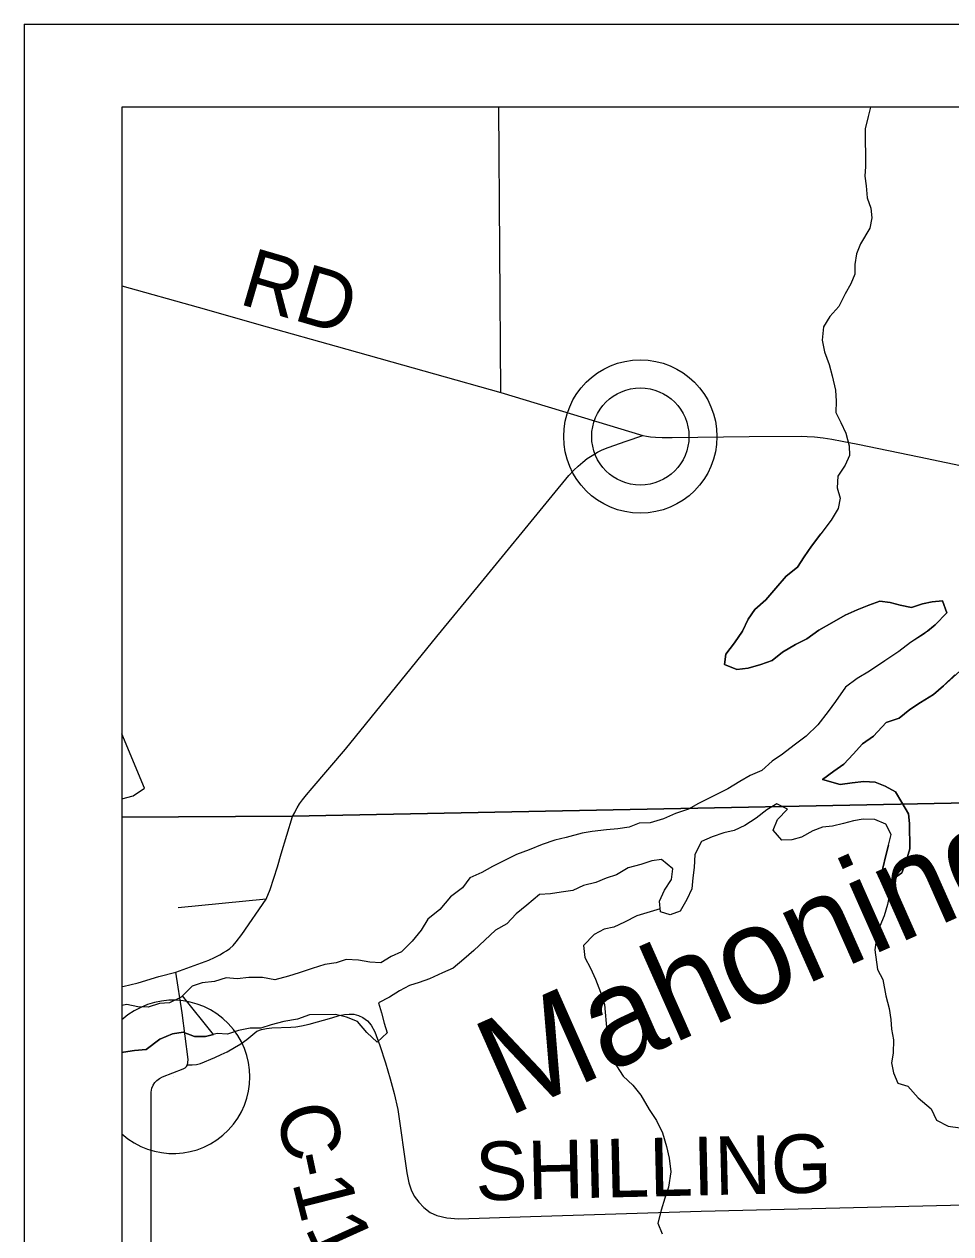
# Model space of a CAD drawing. Extents: x 0 to 34, y 0 to 22.
# Drawn here: x 2.895 to 3.794, y 19.713 to 20.887 of the extents above; entities that cross this region are included whole.
import ezdxf

# ---------------------------------------------------------------- set-up
doc = ezdxf.new("R2010")
doc.units = 0
for name, color, linetype in [('GM_X_Corporation', 7, 'Continuous'), ('GM_X_County_Road', 7, 'Continuous'), ('GM_X_County_Road_Text', 7, 'Continuous'), ('GM_X_Major_Lake', 7, 'Continuous'), ('GM_X_Major_River_Text', 7, 'Continuous'), ('GM_X_Minor_Lake', 7, 'Continuous'), ('GM_X_Minor_River', 7, 'Continuous'), ('GM_X_Township_Road', 7, 'Continuous'), ('GM_X_Unincorporated', 7, 'Continuous'), ('GM_X_Unincorporated_Location', 7, 'Continuous'), ('SH_Data', 7, 'Continuous')]:
    doc.layers.add(name, color=color, linetype=linetype)

msp = doc.modelspace()

# ---------------------------------------------------------------- linework, layer by layer
at = {"layer": 'GM_X_Corporation'}
msp.add_lwpolyline([(7.2136, 20.8069), (2.9895, 20.8069), (2.9895, 20.1176), (3.1549, 20.1187), (4.9925, 20.1548), (5.7004, 20.168), (6.0786, 20.1754), (7.2254, 20.198), (7.2157, 20.6753), (7.2146, 20.7526)], close=True, dxfattribs=at)
msp.add_lwpolyline([(7.2872, 17.1772), (7.283, 17.3071), (7.2799, 17.4174), (7.2764, 17.5202), (7.2751, 17.5764), (7.2467, 19.0557), (7.2468, 19.0896), (7.2426, 19.2998), (7.2392, 19.4543), (7.237, 19.6097), (7.2344, 19.7492), (7.2317, 19.8848), (7.2291, 20.0061), (7.2266, 20.122), (7.2254, 20.198), (6.0786, 20.1754), (5.7004, 20.168), (4.9925, 20.1548), (3.1549, 20.1187), (2.9895, 20.1176), (2.9895, 14.989)], dxfattribs=at)
at = {"layer": 'GM_X_County_Road'}
for points in [[(2.9895, 20.6334), (3.0636, 20.6128), (3.1305, 20.5937), (3.1975, 20.5748), (3.293, 20.5479), (3.3574, 20.5298), (3.4952, 20.4881)], [(3.4952, 20.4881), (3.4988, 20.4874), (3.5026, 20.4869), (3.5076, 20.4866), (3.514, 20.4862), (3.5236, 20.4863), (3.5983, 20.487), (3.6493, 20.4874), (3.6549, 20.4872), (3.662, 20.4867), (3.6704, 20.4858), (3.6788, 20.4846), (3.6888, 20.4827), (3.7038, 20.4797), (3.7635, 20.4674), (3.8622, 20.4468)], [(3.053, 19.8774), (3.0535, 19.8797), (3.0537, 19.8826), (3.0479, 19.9276), (3.0419, 19.9673)], [(3.053, 19.8774), (3.0575, 19.8772), (3.0617, 19.8776), (3.0656, 19.8785), (3.0796, 19.8845), (3.0857, 19.8872), (3.0917, 19.89), (3.0989, 19.894), (3.1048, 19.8978), (3.1108, 19.9018), (3.1205, 19.9099), (3.1249, 19.9117), (3.1299, 19.9127), (3.135, 19.9133), (3.1534, 19.9138), (3.1584, 19.9142), (3.1639, 19.9151), (3.1714, 19.9169), (3.1932, 19.9229), (3.2004, 19.925), (3.2056, 19.926), (3.21, 19.9265), (3.2147, 19.9263), (3.2192, 19.925), (3.2234, 19.9232), (3.2278, 19.9201), (3.2313, 19.9157), (3.2349, 19.9092), (3.24, 19.8962), (3.2454, 19.8792), (3.25, 19.8636), (3.2538, 19.8494), (3.2574, 19.8339), (3.266, 19.7725), (3.2681, 19.7627), (3.2703, 19.7559), (3.2732, 19.7497), (3.2777, 19.744), (3.2827, 19.7388), (3.2887, 19.734), (3.2953, 19.7311), (3.305, 19.7288), (3.3162, 19.7277), (3.386, 19.7302), (3.552, 19.7353), (3.794, 19.7412), (4.0292, 19.747)], [(3.0276, 19.1815), (3.0267, 19.2849), (3.0224, 19.391), (3.0205, 19.4548), (3.0189, 19.5532), (3.0181, 19.6645), (3.0178, 19.7405), (3.018, 19.7974), (3.0177, 19.8507), (3.0185, 19.8545), (3.0197, 19.8575), (3.0215, 19.8602), (3.0233, 19.862), (3.0258, 19.8639), (3.0287, 19.8655), (3.0489, 19.8734), (3.0509, 19.8745), (3.0523, 19.8756), (3.053, 19.8774)]]:
    msp.add_lwpolyline(points, dxfattribs=at)
at = {"layer": 'GM_X_Major_Lake'}
msp.add_line((3.0785, 19.9068), (3.0482, 19.9443), dxfattribs=at)
for points in [[(3.7164, 20.8069), (3.7141, 20.7976), (3.7112, 20.7858), (3.7115, 20.7493), (3.7109, 20.7398), (3.7121, 20.7303), (3.7129, 20.7189), (3.7165, 20.7087), (3.7177, 20.6992), (3.7155, 20.6893), (3.7065, 20.674), (3.7028, 20.6645), (3.701, 20.6542), (3.7011, 20.6447), (3.6973, 20.6352), (3.6917, 20.6256), (3.6854, 20.6134), (3.6767, 20.6035), (3.6707, 20.5935), (3.6693, 20.5806), (3.6717, 20.5692), (3.676, 20.5571), (3.6791, 20.5461), (3.6823, 20.5321), (3.6828, 20.5214), (3.6825, 20.5104), (3.6875, 20.5006), (3.6922, 20.4903), (3.6957, 20.4782), (3.6958, 20.4687), (3.6917, 20.4592), (3.6846, 20.4485), (3.6839, 20.4374), (3.6867, 20.4272), (3.6848, 20.4173), (3.6781, 20.4058), (3.6679, 20.3928)], [(3.6679, 20.3928), (3.6589, 20.3806), (3.6518, 20.3703), (3.6454, 20.3603), (3.6345, 20.3515), (3.6243, 20.34), (3.6145, 20.3286), (3.6039, 20.3193), (3.5976, 20.3098), (3.592, 20.2983), (3.5841, 20.2869), (3.5758, 20.2758), (3.5744, 20.2659), (3.5866, 20.2611), (3.5976, 20.2623), (3.6098, 20.2658), (3.6207, 20.2697), (3.6309, 20.2778), (3.6434, 20.2851), (3.6544, 20.2909), (3.6661, 20.2993), (3.6786, 20.3063), (3.6915, 20.3136), (3.7032, 20.319), (3.7146, 20.3233), (3.7252, 20.3272), (3.7355, 20.3261), (3.745, 20.3235), (3.7561, 20.3213), (3.7667, 20.3248), (3.7762, 20.3268), (3.7861, 20.3277), (3.7903, 20.3159)], [(3.7715, 20.2981), (3.779, 20.3044), (3.7903, 20.3159), (3.7861, 20.3277), (3.7762, 20.3268), (3.7667, 20.3248), (3.7561, 20.3213), (3.745, 20.3235), (3.7355, 20.3261), (3.7252, 20.3272), (3.7146, 20.3233), (3.7032, 20.319), (3.6915, 20.3136), (3.6786, 20.3063), (3.6661, 20.2993), (3.6544, 20.2909), (3.6434, 20.2851), (3.6309, 20.2778), (3.6207, 20.2697), (3.6098, 20.2658), (3.5976, 20.2623), (3.5866, 20.2611), (3.5744, 20.2659), (3.5758, 20.2758), (3.5841, 20.2869), (3.592, 20.2983), (3.5976, 20.3098), (3.6039, 20.3193), (3.6145, 20.3286), (3.6243, 20.34), (3.6345, 20.3515), (3.6454, 20.3603), (3.6518, 20.3703), (3.6589, 20.3806), (3.6679, 20.3928)], [(3.7903, 20.3159), (3.779, 20.3044), (3.7685, 20.2956), (3.7552, 20.2871), (3.7439, 20.2783), (3.7303, 20.2694), (3.7152, 20.2594), (3.7034, 20.2521), (3.6921, 20.2437), (3.6823, 20.2299), (3.6752, 20.2203), (3.6651, 20.2073), (3.6537, 20.1962), (3.642, 20.1874), (3.6307, 20.1789), (3.6209, 20.172), (3.6107, 20.1628), (3.5993, 20.1582), (3.5895, 20.1524), (3.5778, 20.1451), (3.5668, 20.1396), (3.5494, 20.1308), (3.5395, 20.1254), (3.527, 20.1211), (3.5153, 20.116), (3.5024, 20.1121), (3.4917, 20.1117), (3.4819, 20.1078), (3.4708, 20.1062), (3.4598, 20.1053), (3.4461, 20.1037), (3.4363, 20.1021), (3.4207, 20.0978), (3.4097, 20.0954), (3.3976, 20.0912), (3.3847, 20.0861), (3.3726, 20.0814), (3.3623, 20.0764), (3.3491, 20.0699), (3.3389, 20.0641), (3.3271, 20.0587), (3.32, 20.0491), (3.3086, 20.0403), (3.2981, 20.028), (3.2864, 20.0188), (3.28, 20.0081), (3.2714, 19.9974), (3.2608, 19.987), (3.251, 19.9824), (3.2408, 19.9762), (3.2301, 19.9769), (3.2191, 19.9787), (3.2073, 19.9794), (3.1974, 19.9763), (3.1864, 19.9747), (3.1743, 19.9708), (3.1614, 19.9665), (3.1511, 19.9634), (3.1378, 19.9598), (3.126, 19.962), (3.1127, 19.9619), (3.1013, 19.9607), (3.0907, 19.9617), (3.0793, 19.9582), (3.0675, 19.957), (3.0576, 19.9535), (3.0471, 19.9431), (3.0357, 19.9373), (3.0258, 19.9369)], [(3.7715, 20.2981), (3.7552, 20.2871), (3.7439, 20.2783), (3.7303, 20.2694), (3.7152, 20.2594), (3.7034, 20.2521), (3.6921, 20.2437), (3.6823, 20.2299), (3.6752, 20.2203), (3.6651, 20.2073), (3.6537, 20.1962), (3.642, 20.1874), (3.6307, 20.1789), (3.6209, 20.172), (3.6107, 20.1628), (3.5993, 20.1582), (3.5895, 20.1524), (3.5778, 20.1451), (3.5668, 20.1396), (3.5494, 20.1308), (3.5395, 20.1254), (3.527, 20.1211), (3.5153, 20.116), (3.5024, 20.1121), (3.4917, 20.1117), (3.4819, 20.1078), (3.4708, 20.1062), (3.4598, 20.1053), (3.4461, 20.1037), (3.4363, 20.1021), (3.4207, 20.0978), (3.4097, 20.0954), (3.3976, 20.0912), (3.3847, 20.0861), (3.3726, 20.0814), (3.3623, 20.0764), (3.3491, 20.0699), (3.3389, 20.0641), (3.3271, 20.0587), (3.32, 20.0491), (3.3086, 20.0403), (3.2981, 20.028), (3.2864, 20.0188), (3.28, 20.0081), (3.2714, 19.9974), (3.2608, 19.987), (3.251, 19.9824), (3.2408, 19.9762), (3.2301, 19.9769), (3.2191, 19.9787), (3.2073, 19.9794), (3.1974, 19.9763), (3.1864, 19.9747), (3.1743, 19.9708), (3.1614, 19.9665), (3.1511, 19.9634), (3.1378, 19.9598), (3.126, 19.962), (3.1127, 19.9619), (3.1013, 19.9607), (3.0907, 19.9617), (3.0793, 19.9582), (3.0675, 19.957), (3.0576, 19.9535), (3.0471, 19.9431), (3.0357, 19.9373), (3.0258, 19.9369)], [(3.8092, 20.2648), (3.7872, 20.2452), (3.7774, 20.2367), (3.7649, 20.229), (3.7543, 20.2221), (3.7441, 20.2137), (3.7316, 20.2094), (3.7192, 20.1964), (3.7086, 20.1887), (3.6995, 20.1787), (3.6905, 20.1691), (3.6807, 20.1622), (3.6697, 20.1542), (3.6869, 20.1494), (3.6986, 20.151), (3.7097, 20.1522), (3.7207, 20.1515), (3.7306, 20.1478), (3.7406, 20.1422), (3.7467, 20.132), (3.7533, 20.121), (3.7542, 20.1115), (3.7544, 20.0868), (3.7507, 20.0735), (3.7466, 20.0636), (3.7368, 20.0566), (3.7272, 20.0585), (3.7283, 20.0683), (3.7312, 20.0805), (3.7338, 20.0904)], [(3.7338, 20.0904), (3.7312, 20.0805), (3.7283, 20.0683), (3.7272, 20.0585), (3.7368, 20.0566), (3.7466, 20.0636), (3.7507, 20.0735), (3.7544, 20.0868), (3.7542, 20.1115), (3.7533, 20.121), (3.7467, 20.132), (3.7406, 20.1422), (3.7306, 20.1478), (3.7207, 20.1515), (3.7097, 20.1522), (3.6986, 20.151), (3.6869, 20.1494), (3.6697, 20.1542), (3.6807, 20.1622), (3.6905, 20.1691), (3.6995, 20.1787), (3.7086, 20.1887), (3.7192, 20.1964), (3.7316, 20.2094), (3.7441, 20.2137), (3.7543, 20.2221), (3.7649, 20.229), (3.7774, 20.2367), (3.7872, 20.2452), (3.7981, 20.2559)], [(3.7338, 20.0904), (3.7364, 20.1007), (3.731, 20.1109), (3.7206, 20.1154), (3.7092, 20.1157), (3.6997, 20.1141), (3.6899, 20.1114), (3.6792, 20.109), (3.6697, 20.1078), (3.6603, 20.1043), (3.6493, 20.0981), (3.6398, 20.0958), (3.6303, 20.0953), (3.6219, 20.1051), (3.6259, 20.1154), (3.6357, 20.1254), (3.6254, 20.1306), (3.6156, 20.1248), (3.6054, 20.1168), (3.5944, 20.1095), (3.5838, 20.1048), (3.5739, 20.1025), (3.5626, 20.0986), (3.5523, 20.0939), (3.5456, 20.0813), (3.545, 20.0688), (3.5439, 20.0589), (3.5429, 20.0482), (3.538, 20.0379), (3.5313, 20.0265), (3.5218, 20.023), (3.5123, 20.0259), (3.5114, 20.0362), (3.5163, 20.0469), (3.523, 20.0572), (3.5244, 20.0675), (3.5133, 20.0765), (3.5038, 20.0753), (3.4932, 20.0718), (3.4811, 20.0686), (3.4697, 20.0617), (3.4595, 20.0586), (3.4496, 20.0543), (3.4375, 20.0512), (3.4273, 20.0465), (3.4159, 20.0449), (3.4056, 20.0433), (3.395, 20.0425), (3.3825, 20.0321), (3.3723, 20.0237), (3.3633, 20.0141), (3.3523, 20.0079), (3.3417, 19.9983), (3.3312, 19.9884), (3.3214, 19.9799), (3.3112, 19.9711), (3.3006, 19.9665), (3.2881, 19.9607), (3.2782, 19.9572), (3.2687, 19.9544), (3.2589, 19.949), (3.2491, 19.9429), (3.2384, 19.9375), (3.2416, 19.9276), (3.244, 19.9177), (3.2471, 19.9083), (3.2373, 19.8994), (3.2273, 19.9085), (3.2181, 19.9194), (3.2074, 19.9235), (3.1967, 19.9261), (3.1716, 19.9259), (3.1599, 19.9216), (3.1466, 19.9192), (3.1344, 19.9161), (3.1242, 19.913), (3.1139, 19.9129), (3.1025, 19.9105), (3.0919, 19.907), (3.082, 19.9077), (3.0706, 19.9049), (3.06, 19.9049), (3.0489, 19.9089), (3.0387, 19.9073), (3.0262, 19.9023), (3.0129, 19.8923), (3.0015, 19.8911), (2.9909, 19.8895), (2.9895, 19.8892)], [(3.0258, 19.9369), (3.0148, 19.9334), (3.005, 19.9337), (2.9943, 19.9359), (2.9895, 19.9348)], [(3.0482, 19.9443), (3.0471, 19.9431), (3.0357, 19.9373), (3.0258, 19.9369)], [(2.9895, 19.8892), (2.9909, 19.8895), (3.0015, 19.8911), (3.0129, 19.8923), (3.0262, 19.9023), (3.0387, 19.9073), (3.0489, 19.9089), (3.06, 19.9049), (3.0706, 19.9049), (3.0785, 19.9068)]]:
    msp.add_lwpolyline(points, dxfattribs=at)
at = {"layer": 'GM_X_Minor_Lake'}
msp.add_line((3.0114, 20.1458), (2.9895, 20.1984), dxfattribs=at)
msp.add_lwpolyline([(2.9895, 20.1355), (3.0004, 20.1385), (3.0114, 20.1458)], dxfattribs=at)
at = {"layer": 'GM_X_Minor_River'}
for points in [[(3.7322, 20.0575), (3.735, 20.0441), (3.7328, 20.033), (3.7295, 20.022), (3.7254, 20.0117), (3.7224, 20.0022), (3.7206, 19.9889), (3.7231, 19.9699), (3.7281, 19.96), (3.7313, 19.9441), (3.7345, 19.9319), (3.7361, 19.9213), (3.7366, 19.9118), (3.7385, 19.9016), (3.7383, 19.8887), (3.7368, 19.8791), (3.7385, 19.8696), (3.7427, 19.8594), (3.7526, 19.8565), (3.7626, 19.8451), (3.7753, 19.8346), (3.7803, 19.8236), (3.7918, 19.8176), (3.8032, 19.8162)], [(3.512, 20.0287), (3.4895, 20.022), (3.4774, 20.0158), (3.4671, 20.0108), (3.4576, 20.0088), (3.4478, 20.0038), (3.4376, 19.993), (3.4389, 19.9813), (3.4443, 19.971), (3.4493, 19.9604), (3.454, 19.9479), (3.4579, 19.9358), (3.4604, 19.91), (3.4609, 19.8982), (3.4633, 19.8876), (3.4695, 19.8762), (3.476, 19.8664), (3.4856, 19.8577), (3.4933, 19.8479), (3.5014, 19.8339), (3.5084, 19.8233), (3.5142, 19.8112), (3.5181, 19.7979), (3.5209, 19.7866), (3.5225, 19.7733), (3.52, 19.7584), (3.5167, 19.7478), (3.513, 19.7363), (3.5097, 19.7237), (3.5139, 19.7131)]]:
    msp.add_lwpolyline(points, dxfattribs=at)
at = {"layer": 'GM_X_Township_Road'}
for p, q in [((3.3574, 20.5298), (3.3555, 20.8069)), ((3.1296, 20.0382), (3.0442, 20.0297))]:
    msp.add_line(p, q, dxfattribs=at)
for points in [[(3.1576, 20.123), (3.1595, 20.1266), (3.162, 20.1305), (3.1647, 20.1344), (3.1685, 20.1394), (3.1743, 20.1457), (3.2064, 20.1836), (3.2953, 20.2931), (3.3357, 20.3423), (3.4073, 20.4296), (3.4232, 20.4494), (3.4283, 20.4546), (3.4324, 20.4582), (3.4369, 20.4621), (3.4413, 20.4657), (3.446, 20.4687), (3.4513, 20.4719), (3.4556, 20.4741), (3.4616, 20.4766), (3.4791, 20.4825), (3.4952, 20.4881)], [(3.0419, 19.9673), (3.0738, 19.979), (3.0792, 19.9814), (3.0846, 19.9841), (3.0882, 19.9862), (3.0909, 19.988), (3.0941, 19.9902), (3.0973, 19.9932), (3.1004, 19.9966), (3.106, 20.0037), (3.1296, 20.0382), (3.1333, 20.0474), (3.1369, 20.0583), (3.1404, 20.0696), (3.1439, 20.0821), (3.1551, 20.1182), (3.1572, 20.1221), (3.1576, 20.123)], [(2.9895, 19.9534), (2.9916, 19.9537), (2.9972, 19.9548), (3.0052, 19.957), (3.0252, 19.9629), (3.0419, 19.9673)]]:
    msp.add_lwpolyline(points, dxfattribs=at)
at = {"layer": 'GM_X_Unincorporated'}
msp.add_line((2.9895, 19.921), (2.9895, 19.8102), dxfattribs=at)
for radius in [0.0744, 0.0472]:
    msp.add_circle((3.4928, 20.4871), radius, dxfattribs=at)
msp.add_arc((3.0392, 19.8656), 0.0744, 228.1056, 131.8944, dxfattribs=at)
at = {"layer": 'GM_X_Unincorporated_Location'}
for p, q in [((3.4928, 20.4871), (3.4928, 20.4871)), ((3.0392, 19.8656), (3.0392, 19.8656))]:
    msp.add_line(p, q, dxfattribs=at)
at = {"layer": 'SH_Data'}
for q in [(9.8945, 20.8873), (2.8945, 13.8873)]:
    msp.add_line((2.8945, 20.8873), q, dxfattribs=at)

# ---------------------------------------------------------------- texts
at = {"layer": 'GM_X_County_Road_Text'}
for s, height, rotation, p in [('RD', 0.05682, 343.7179, (3.1017, 20.6162)), ('C', 0.0568, 283.6046, (3.1382, 19.8334)), ('SHILLING', 0.05682, 1.3347, (3.3331, 19.7455)), ('-', 0.0568, 282.031, (3.149, 19.7885)), ('1', 0.0568, 284.2704, (3.1545, 19.7633)), ('1', 0.0568, 294.2824, (3.1667, 19.7192))]:
    msp.add_text(s, height=height, rotation=rotation, dxfattribs=at).set_placement(p)
at = {"layer": 'GM_X_Major_River_Text'}
msp.add_text('Mahoning', height=0.09473, rotation=23.9275, dxfattribs=at).set_placement((3.3633, 19.8261))

doc.saveas('drawing.dxf')
